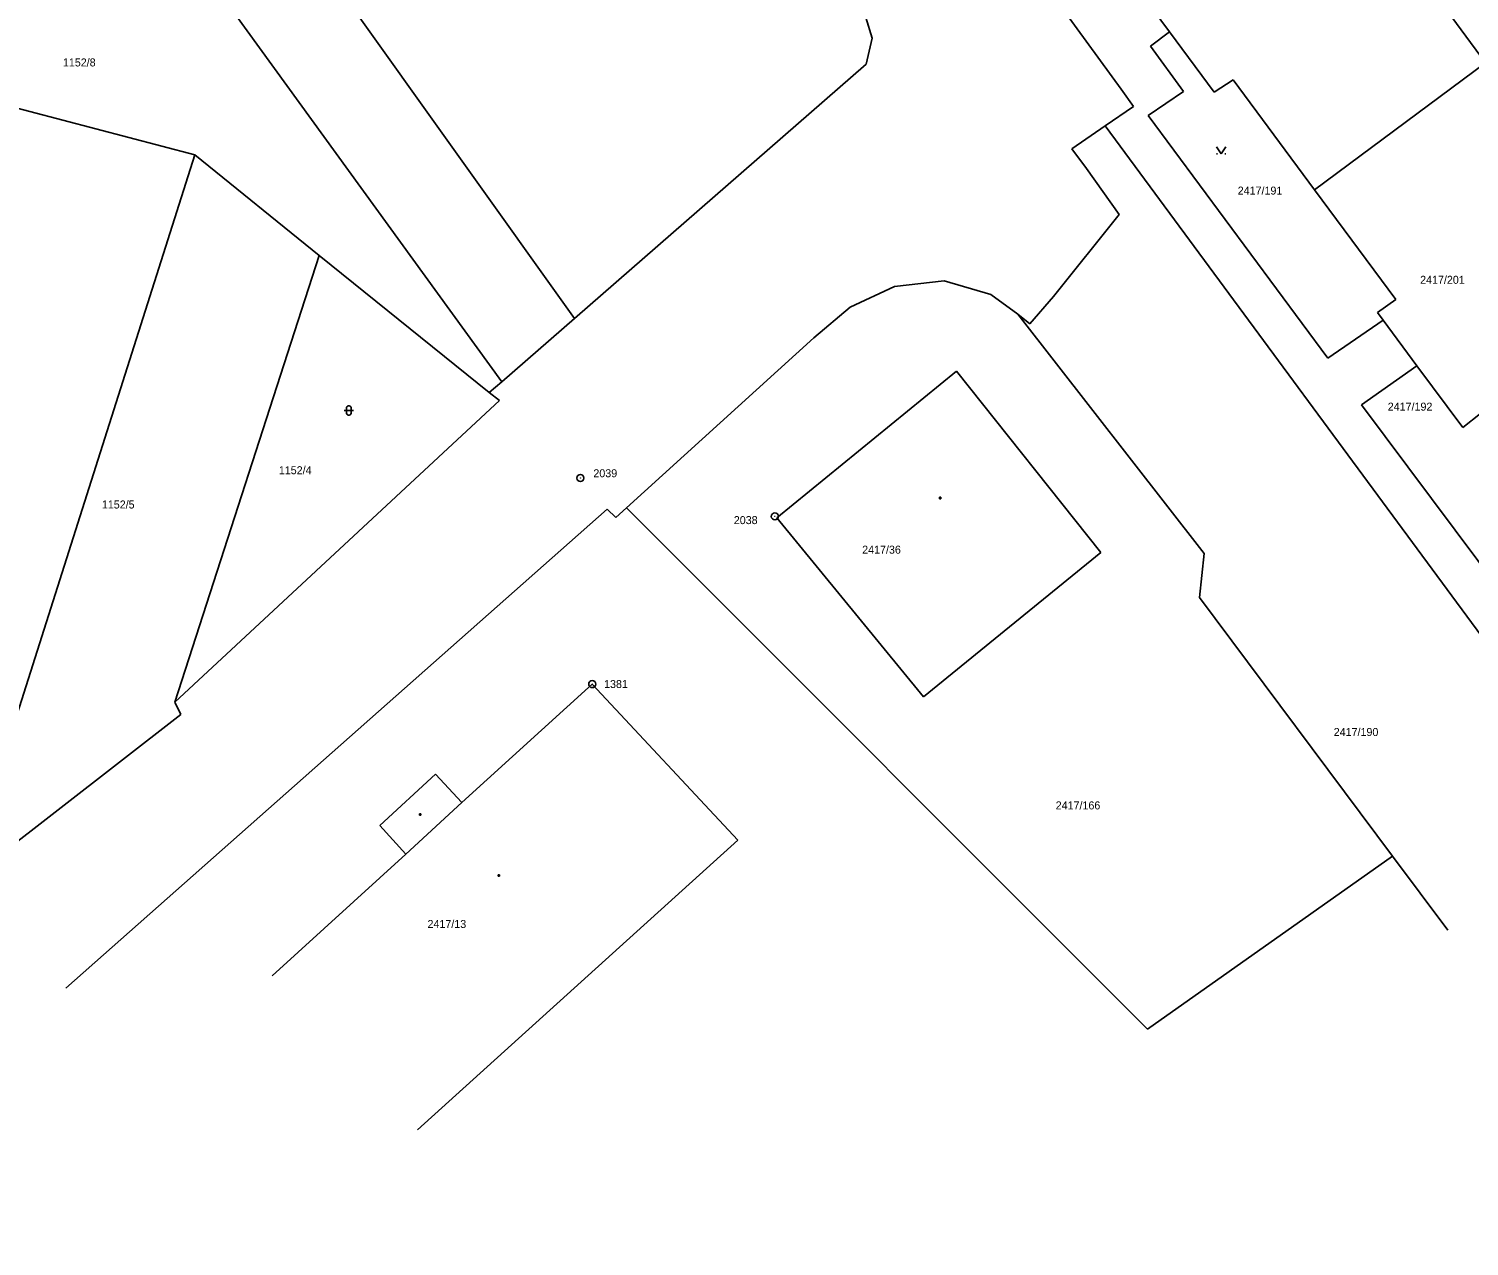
# Model space of a CAD drawing. Extents: x -609709 to -609357, y -1051535 to -1051131.
# Drawn here: x -609619.2 to -609542.7, y -1051503.8 to -1051439.1 of the extents above; entities that cross this region are included whole.
import ezdxf

# ---------------------------------------------------------------- set-up
doc = ezdxf.new("R2010")
doc.units = 0
doc.layers.add('Vrstva 10', color=7, linetype='Continuous')

msp = doc.modelspace()

# ---------------------------------------------------------------- linework, layer by layer
at = {"layer": 'Vrstva 10'}
for p, q in [((-609582.56, -1051412.81), (-609561.16, -1051442.27)), ((-609609.81, -1051426.95), (-609590.2, -1051454.46)), ((-609548.51, -1051431.78), (-609541.79, -1051440.87)), ((-609612.82, -1051431.94), (-609594.06, -1051457.83)), ((-609575.25, -1051436.72), (-609574.38, -1051439.57)), ((-609560.37, -1051436.81), (-609558.58, -1051439.23)), ((-609574.7, -1051440.95), (-609574.38, -1051439.57)), ((-609559.6, -1051439.99), (-609558.58, -1051439.23)), ((-609558.58, -1051439.23), (-609556.21, -1051442.43)), ((-609633.53, -1051439.67), (-609610.36, -1051445.77)), ((-609559.6, -1051439.99), (-609557.84, -1051442.4)), ((-609590.2, -1051454.46), (-609574.7, -1051440.95)), ((-609550.88, -1051447.62), (-609541.79, -1051440.87)), ((-609556.21, -1051442.43), (-609555.2, -1051441.78)), ((-609555.2, -1051441.78), (-609550.88, -1051447.62)), ((-609561.16, -1051442.27), (-609560.49, -1051443.19)), ((-609559.72, -1051443.68), (-609557.84, -1051442.4)), ((-609562.01, -1051444.23), (-609560.49, -1051443.19)), ((-609559.72, -1051443.68), (-609550.17, -1051456.58)), ((-609563.77, -1051445.44), (-609562.01, -1051444.23)), ((-609562.01, -1051444.23), (-609518.11, -1051503.76)), ((-609563.77, -1051445.44), (-609563, -1051446.49)), ((-609556.09, -1051445.335), (-609555.84, -1051445.71)), ((-609555.84, -1051445.71), (-609555.59, -1051445.335)), ((-609621.62, -1051481.19), (-609610.36, -1051445.77)), ((-609610.36, -1051445.77), (-609603.75, -1051451.11)), ((-609556.09, -1051445.71), (-609556.04, -1051445.71)), ((-609555.64, -1051445.71), (-609555.59, -1051445.71)), ((-609563, -1051446.49), (-609561.26, -1051448.93)), ((-609550.88, -1051447.62), (-609546.56, -1051453.45)), ((-609564.74, -1051453.3), (-609561.26, -1051448.93)), ((-609611.43, -1051474.86), (-609603.75, -1051451.11)), ((-609603.75, -1051451.11), (-609594.72, -1051458.4)), ((-609573.19, -1051452.77), (-609570.55, -1051452.47)), ((-609570.55, -1051452.47), (-609568.08, -1051453.19)), ((-609575.54, -1051453.87), (-609573.19, -1051452.77)), ((-609568.08, -1051453.19), (-609566.64, -1051454.24)), ((-609566, -1051454.75), (-609564.74, -1051453.3)), ((-609577.48, -1051455.5), (-609575.54, -1051453.87)), ((-609547.54, -1051454.15), (-609546.56, -1051453.45)), ((-609594.06, -1051457.83), (-609590.2, -1051454.46)), ((-609566.64, -1051454.24), (-609556.74, -1051466.95)), ((-609566.64, -1051454.24), (-609566, -1051454.75)), ((-609550.17, -1051456.58), (-609547.23, -1051454.56)), ((-609547.54, -1051454.15), (-609547.23, -1051454.56)), ((-609547.23, -1051454.56), (-609545.44, -1051456.98)), ((-609587.43, -1051464.52), (-609577.48, -1051455.5)), ((-609548.38, -1051459.06), (-609545.44, -1051456.98)), ((-609545.44, -1051456.98), (-609543.01, -1051460.25)), ((-609594.72, -1051458.4), (-609594.06, -1051457.83)), ((-609579.45, -1051465.05), (-609569.9, -1051457.27)), ((-609569.9, -1051457.27), (-609562.23, -1051466.9)), ((-609594.72, -1051458.4), (-609594.18, -1051458.83)), ((-609611.43, -1051474.86), (-609594.18, -1051458.83)), ((-609602.43, -1051459.35), (-609601.93, -1051459.35)), ((-609602.305, -1051459.2), (-609602.28, -1051459.15)), ((-609602.305, -1051459.5), (-609602.305, -1051459.2)), ((-609602.28, -1051459.15), (-609602.255, -1051459.125)), ((-609602.255, -1051459.125), (-609602.205, -1051459.1)), ((-609602.205, -1051459.1), (-609602.155, -1051459.1)), ((-609602.155, -1051459.1), (-609602.105, -1051459.125)), ((-609602.105, -1051459.125), (-609602.08, -1051459.15)), ((-609602.08, -1051459.15), (-609602.055, -1051459.2)), ((-609602.055, -1051459.2), (-609602.055, -1051459.5)), ((-609548.38, -1051459.06), (-609539.42, -1051471.07)), ((-609602.28, -1051459.55), (-609602.305, -1051459.5)), ((-609602.255, -1051459.575), (-609602.28, -1051459.55)), ((-609602.205, -1051459.6), (-609602.255, -1051459.575)), ((-609602.155, -1051459.6), (-609602.205, -1051459.6)), ((-609602.105, -1051459.575), (-609602.155, -1051459.6)), ((-609602.08, -1051459.55), (-609602.105, -1051459.575)), ((-609602.055, -1051459.5), (-609602.08, -1051459.55)), ((-609543.01, -1051460.25), (-609542.07, -1051459.52)), ((-609570.805, -1051463.965), (-609570.73, -1051463.965)), ((-609570.805, -1051464.04), (-609570.805, -1051463.965)), ((-609570.73, -1051464.04), (-609570.805, -1051464.04)), ((-609570.73, -1051463.965), (-609570.73, -1051464.04)), ((-609617.22, -1051490.05), (-609588.46, -1051464.6)), ((-609588.46, -1051464.6), (-609587.99, -1051465.03)), ((-609587.99, -1051465.03), (-609587.43, -1051464.52)), ((-609587.43, -1051464.52), (-609559.76, -1051492.22)), ((-609579.45, -1051465.05), (-609571.65, -1051474.57)), ((-609571.65, -1051474.57), (-609562.23, -1051466.9)), ((-609556.99, -1051469.29), (-609556.74, -1051466.95)), ((-609556.99, -1051469.29), (-609546.74, -1051483.03)), ((-609596.18, -1051480.19), (-609589.25, -1051473.89)), ((-609589.25, -1051473.89), (-609581.52, -1051482.18)), ((-609625.48, -1051486.67), (-609611.11, -1051475.5)), ((-609611.43, -1051474.86), (-609611.11, -1051475.5)), ((-609603.86, -1051478.23), (-609603.86, -1051478.23)), ((-609604.82, -1051479.08), (-609604.82, -1051479.08)), ((-609600.54, -1051481.4), (-609597.57, -1051478.68)), ((-609597.57, -1051478.68), (-609596.18, -1051480.19)), ((-609599.16, -1051482.92), (-609596.18, -1051480.19)), ((-609598.425, -1051480.785), (-609598.35, -1051480.785)), ((-609598.425, -1051480.86), (-609598.425, -1051480.785)), ((-609598.35, -1051480.86), (-609598.425, -1051480.86)), ((-609598.35, -1051480.785), (-609598.35, -1051480.86)), ((-609600.54, -1051481.4), (-609599.16, -1051482.92)), ((-609598.54, -1051497.57), (-609581.52, -1051482.18)), ((-609606.25, -1051489.39), (-609599.16, -1051482.92)), ((-609559.76, -1051492.22), (-609546.74, -1051483.03)), ((-609546.74, -1051483.03), (-609543.8, -1051486.96)), ((-609594.245, -1051484.025), (-609594.17, -1051484.025)), ((-609594.245, -1051484.1), (-609594.245, -1051484.025)), ((-609594.17, -1051484.1), (-609594.245, -1051484.1)), ((-609594.17, -1051484.025), (-609594.17, -1051484.1))]:
    msp.add_line(p, q, dxfattribs=at)
for centre, radius in [((-609589.88, -1051462.94), 0.188), ((-609589.88, -1051462.94), 0.0025), ((-609579.55, -1051464.98), 0.188), ((-609579.55, -1051464.98), 0.0025), ((-609589.25, -1051473.89), 0.188), ((-609589.25, -1051473.89), 0.0025)]:
    msp.add_circle(centre, radius, dxfattribs=at)

# ---------------------------------------------------------------- texts
for s, p in [('1152/8', (-609617.37, -1051441.07)), ('2417/191', (-609554.96, -1051447.88)), ('2417/201', (-609545.27, -1051452.62)), ('2417/192', (-609546.99, -1051459.36)), ('1152/4', (-609605.9, -1051462.74)), ('2039', (-609589.19, -1051462.9)), ('1152/5', (-609615.3, -1051464.56)), ('2038', (-609581.73, -1051465.39)), ('2417/36', (-609574.91, -1051466.96)), ('1381', (-609588.621, -1051474.1)), ('2417/190', (-609549.86, -1051476.65)), ('2417/166', (-609564.63, -1051480.55)), ('2417/13', (-609598, -1051486.85))]:
    msp.add_text(s, height=0.425, dxfattribs=at).set_placement(p)

doc.saveas('drawing.dxf')
